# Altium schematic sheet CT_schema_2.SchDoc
size 271 x 273 mm
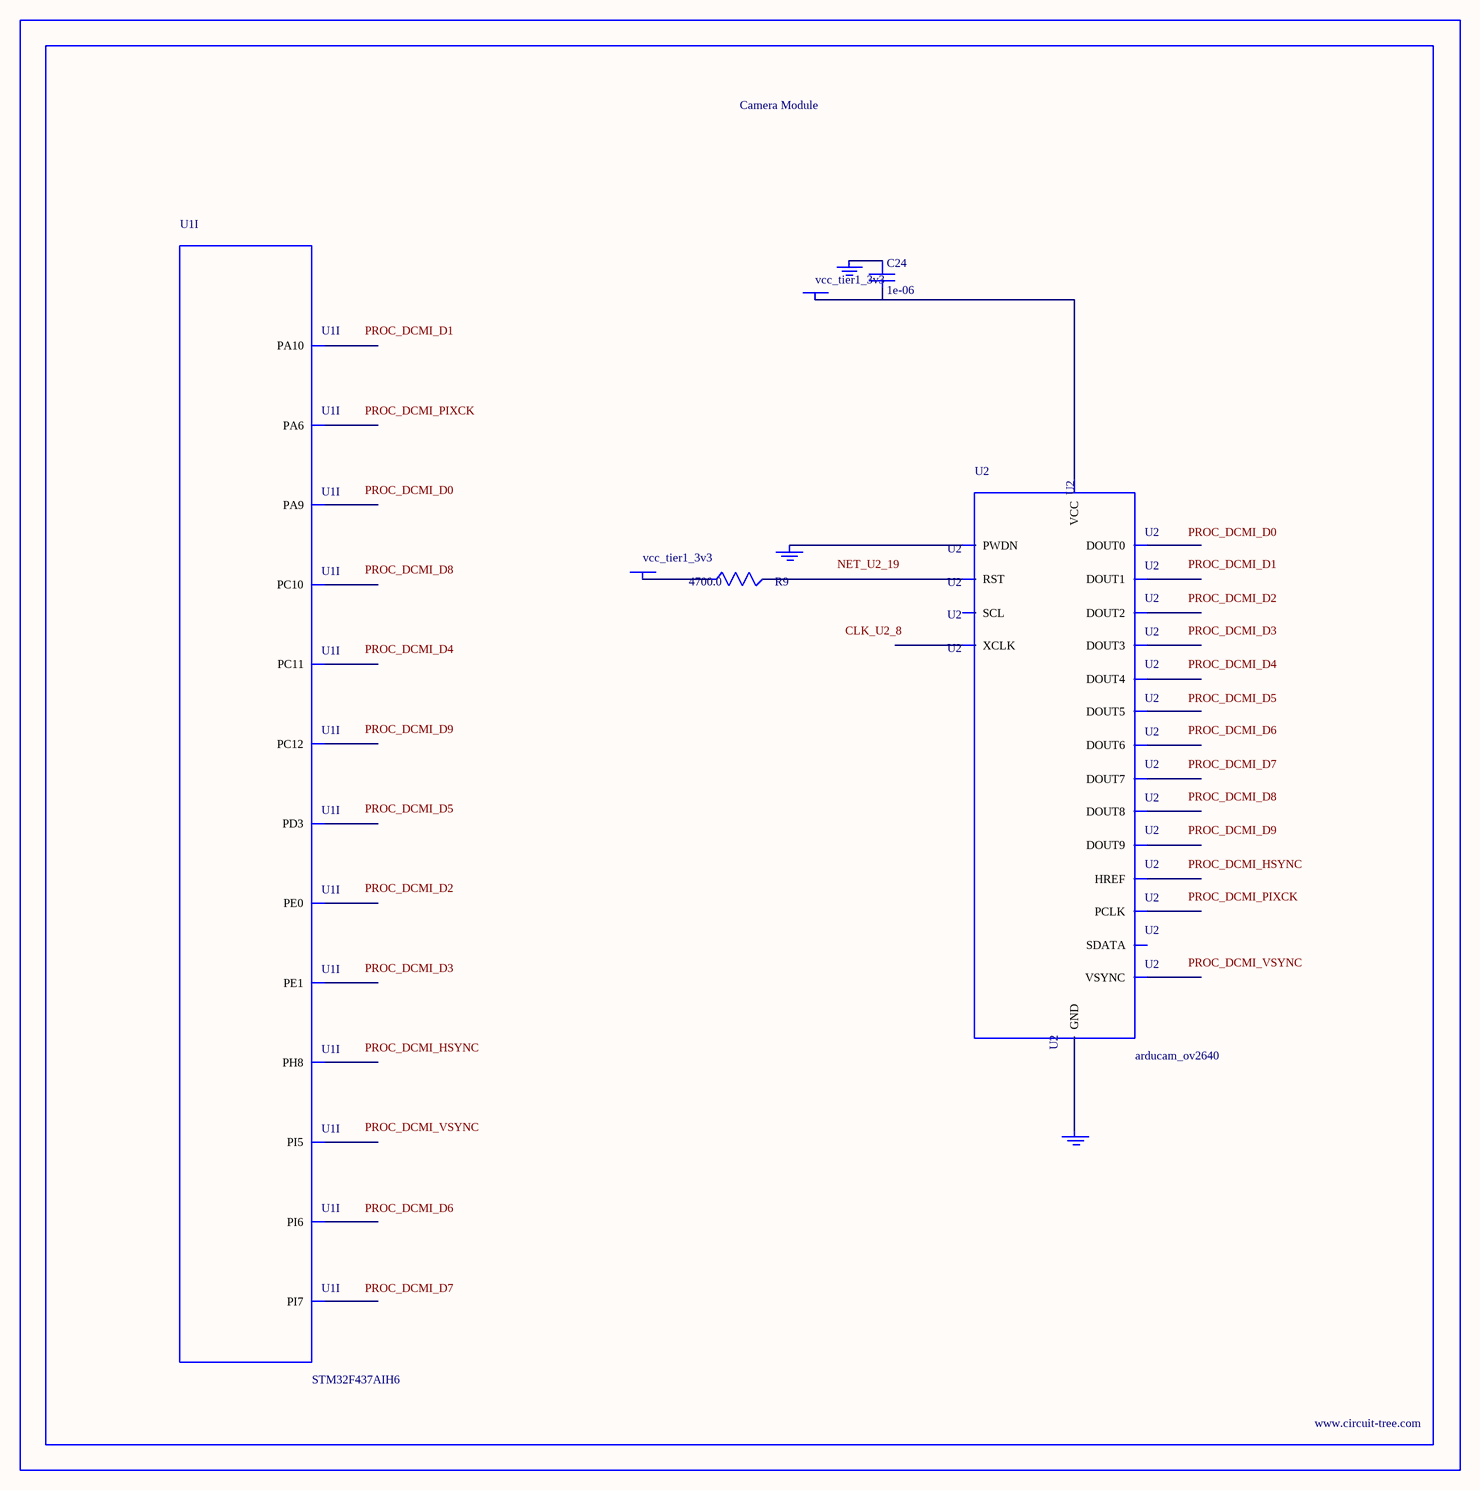
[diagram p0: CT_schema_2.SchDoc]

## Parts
BORDER1  (no value)
C24  1e-06  [C0603]
GND_INSTANCE_1_0  (no value)
GND_INSTANCE_1_1  (no value)
GND_INSTANCE_1_2  (no value)
POWER_INSTANCE_1_0  vcc_tier1_3v3
POWER_INSTANCE_1_1  vcc_tier1_3v3
R9  4700.0  [R0603]
U1  STM32F437AIH6  [UFBGA169]  (part I of 12)
U2  arducam_ov2640  [ARDUCAM]

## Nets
NetC24_1: C24.1 GND_INSTANCE_1_0.0(GND)
NetC24_2: C24.2 POWER_INSTANCE_1_0.0(PWR) U2.1(VCC)
NetGND_INSTANCE_1_1_0: GND_INSTANCE_1_1.0(GND) U2.20(PWDN)
NetGND_INSTANCE_1_2_0: GND_INSTANCE_1_2.0(GND) U2.2(GND)
NetPOWER_INSTANCE_1_1_0: POWER_INSTANCE_1_1.0(PWR) R9.1
NetR9_2: R9.2 U2.19(RST)

Not connected (* = marked no-connect by the designer): U1 A2(PI6) A3(PI5) A4(PE1) A9(PD3) A10(PC12) B1(PI7) B4(PE0) B10(PC11) C10(PC10) E8(PA9) E9(PA10) L10(PH8) N3(PA6); U2 3(SCL) 4(SDATA) 5(VSYNC) 6(HREF) 7(PCLK) 8(XCLK) 9(DOUT9) 10(DOUT8) 11(DOUT7) 12(DOUT6) 13(DOUT5) 14(DOUT4) 15(DOUT3) 16(DOUT2) 17(DOUT1) 18(DOUT0)

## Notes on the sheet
- Labels drawn without touching a wire or pin: CLK_U2_8, NET_U2_19, PROC_DCMI_D0, PROC_DCMI_D1, PROC_DCMI_D2, PROC_DCMI_D3, PROC_DCMI_D4, PROC_DCMI_D5, PROC_DCMI_D6, PROC_DCMI_D7, PROC_DCMI_D8, PROC_DCMI_D9, PROC_DCMI_HSYNC, PROC_DCMI_PIXCK, PROC_DCMI_VSYNC

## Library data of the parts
BORDER1 = BORDER_PAGE1
C24 = C0603C105K3RACTU
GND_INSTANCE_1_0-GND_INSTANCE_1_2 = GND
POWER_INSTANCE_1_0 POWER_INSTANCE_1_1 = PWR
R9 = RC0603JR-074K7L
